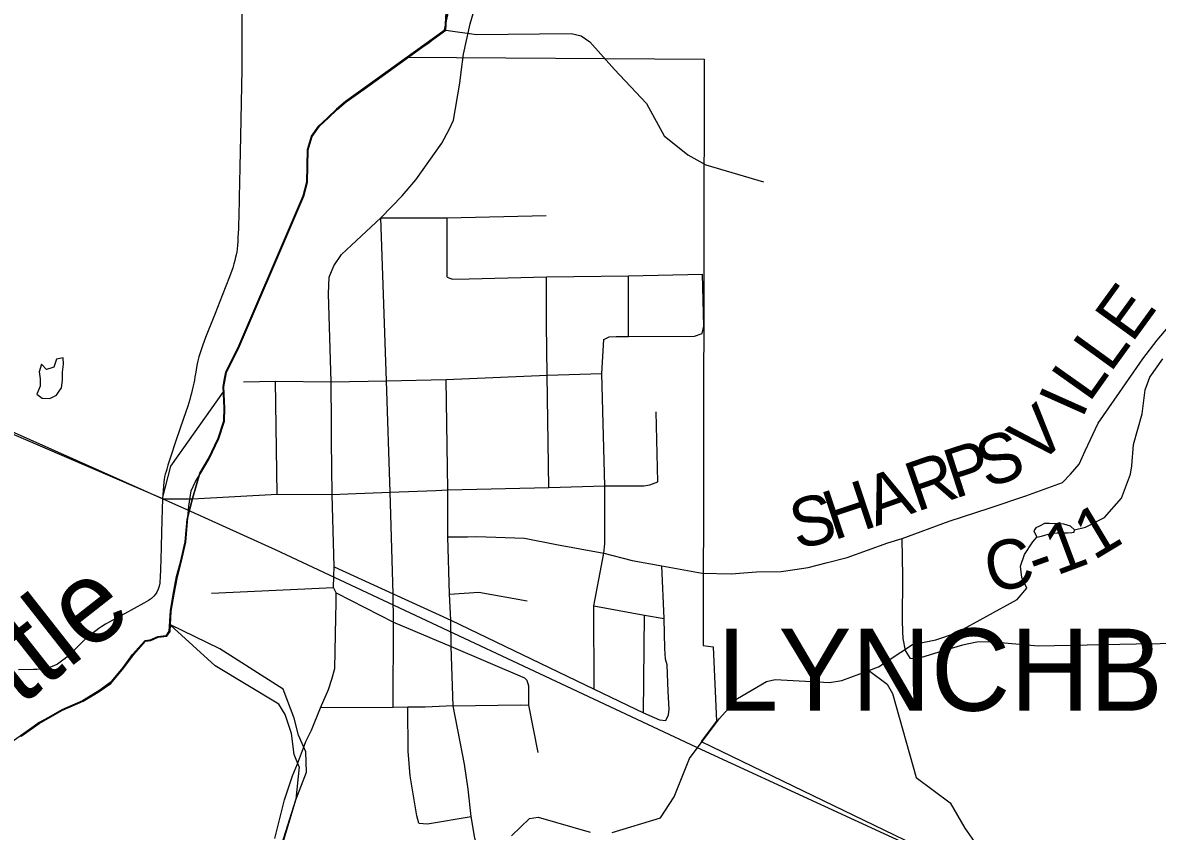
# Model space of a CAD drawing. Extents: x 0 to 1052, y -194 to 246.
# Drawn here: x 2.825 to 4.134, y 14.787 to 15.72 of the extents above; entities that cross this region are included whole.
import ezdxf

# ---------------------------------------------------------------- set-up
doc = ezdxf.new("R2010")
doc.units = 0
for name, color, linetype in [('GM_X_City_Street', 7, 'Continuous'), ('GM_X_Corporation', 7, 'Continuous'), ('GM_X_Corporation_Text', 7, 'Continuous'), ('GM_X_County_Road', 7, 'Continuous'), ('GM_X_County_Road_Text', 7, 'Continuous'), ('GM_X_Major_River', 7, 'Continuous'), ('GM_X_Major_River_Text', 7, 'Continuous'), ('GM_X_Minor_Lake', 7, 'Continuous'), ('GM_X_Minor_River', 7, 'Continuous'), ('GM_X_Rail_Line', 7, 'Continuous'), ('GM_X_State_Route', 7, 'Continuous'), ('GM_X_Township_Road', 7, 'Continuous')]:
    doc.layers.add(name, color=color, linetype=linetype)

msp = doc.modelspace()

# ---------------------------------------------------------------- linework, layer by layer
at = {"layer": 'GM_X_City_Street'}
for p, q in [((3.3148, 15.4262), (3.3148, 15.4949)), ((3.5238, 15.358), (3.5241, 15.4277)), ((3.1186, 15.1761), (3.1169, 15.3065)), ((3.5577, 15.1904), (3.556, 15.271)), ((3.3154, 15.1268), (3.3155, 15.172)), ((3.0431, 15.0619), (3.1835, 15.0686)), ((3.5414, 14.9237), (3.5423, 15.0365)), ((3.4087, 14.9328), (3.4193, 14.8783))]:
    msp.add_line(p, q, dxfattribs=at)
for points in [[(3.2384, 15.4949), (3.3148, 15.4949), (3.4288, 15.4973)], [(3.2525, 14.9299), (3.2529, 15.0284), (3.2524, 15.0612), (3.2491, 15.1784), (3.2447, 15.3069), (3.2384, 15.4949)], [(3.3148, 15.4262), (3.3209, 15.4238), (3.3402, 15.4242), (3.4293, 15.4266), (3.5241, 15.4277), (3.6094, 15.4299)], [(3.609, 15.3612), (3.6108, 15.3696), (3.6094, 15.4299)], [(3.4322, 15.1839), (3.4302, 15.3134), (3.4293, 15.372), (3.4293, 15.4266)], [(3.4844, 14.9511), (3.4841, 15.0474), (3.4956, 15.1079), (3.4966, 15.1187), (3.4967, 15.1858), (3.4933, 15.3152), (3.4953, 15.3544)], [(3.4953, 15.3544), (3.5015, 15.3573), (3.5098, 15.358), (3.5238, 15.358), (3.6002, 15.3582), (3.609, 15.3612)], [(3.0797, 15.3056), (3.1169, 15.3065), (3.1808, 15.3057), (3.2447, 15.3069), (3.3136, 15.3082), (3.4302, 15.3134), (3.4933, 15.3152)], [(3.3155, 15.172), (3.3155, 15.1811), (3.3136, 15.3082)], [(3.2001, 15.1764), (3.2491, 15.1784), (3.3017, 15.1804), (3.3155, 15.1811), (3.4322, 15.1839), (3.4967, 15.1858), (3.5417, 15.1857), (3.5486, 15.187), (3.5577, 15.1904)], [(3.0212, 15.1706), (3.1186, 15.1761), (3.1822, 15.1756), (3.2001, 15.1764)], [(3.3154, 15.1268), (3.3381, 15.1269), (3.3486, 15.1272), (3.4039, 15.1254), (3.4408, 15.1179), (3.4956, 15.1079), (3.5282, 15.0994), (3.5624, 15.0933)], [(3.3215, 14.9319), (3.3194, 15.0003), (3.3188, 15.0309), (3.3175, 15.0606), (3.3154, 15.1268)], [(3.1843, 15.0923), (3.2524, 15.0612), (3.3188, 15.0309), (3.4844, 14.9511), (3.5414, 14.9237), (3.5596, 14.916), (3.567, 14.9151)], [(3.566, 14.9979), (3.5651, 15.0326), (3.5624, 15.0933)], [(3.1869, 15.0623), (3.2529, 15.0284), (3.3194, 15.0003), (3.4038, 14.9643), (3.4066, 14.9617), (3.4087, 14.9552), (3.4087, 14.9328)], [(3.3175, 15.0606), (3.3512, 15.063), (3.4072, 15.0532)], [(3.4841, 15.0474), (3.5423, 15.0365), (3.5651, 15.0326)], [(3.567, 14.9151), (3.5699, 14.9215), (3.5708, 14.9282), (3.5696, 14.9484), (3.5686, 14.9791), (3.5664, 14.9859), (3.566, 14.9979)], [(3.3215, 14.9319), (3.3991, 14.9333), (3.4087, 14.9328)], [(3.2819, 14.7965), (3.2796, 14.805), (3.2721, 14.8511), (3.2698, 14.8796), (3.2693, 14.9304)], [(3.2819, 14.7965), (3.2922, 14.7957), (3.3425, 14.8045)]]:
    msp.add_lwpolyline(points, dxfattribs=at)
at = {"layer": 'GM_X_Corporation'}
for points in [[(3.3184, 15.8132), (3.3123, 15.7116), (3.1976, 15.629), (3.1871, 15.6201), (3.1767, 15.61), (3.1666, 15.6007), (3.1584, 15.5887), (3.1536, 15.5736), (3.1532, 15.5546), (3.1528, 15.5364), (3.1487, 15.5201), (3.136, 15.4904), (3.0743, 15.3472), (3.0593, 15.3167), (3.0576, 15.3073), (3.0563, 15.3), (3.0574, 15.2757), (3.0571, 15.2605), (3.0506, 15.2405), (3.0395, 15.2172), (3.0293, 15.2003), (3.0209, 15.1712), (3.0148, 15.1473), (3.0126, 15.1212), (3.0072, 15.0977), (3.0027, 15.0811), (2.9988, 15.0604), (2.9955, 15.0414), (2.9943, 15.0182), (2.9908, 15.0126), (2.9805, 15.0116), (2.972, 15.0076), (2.966, 15.007), (2.952, 14.9913), (2.9411, 14.9763), (2.9259, 14.958), (2.9112, 14.948), (2.894, 14.9377), (2.8702, 14.9272), (2.8433, 14.9121), (2.8225, 14.8973)], [(2.8225, 14.8973), (2.8433, 14.9121), (2.8702, 14.9272), (2.894, 14.9377), (2.9112, 14.948), (2.9259, 14.958), (2.9411, 14.9763), (2.952, 14.9913), (2.966, 15.007), (2.972, 15.0076), (2.9805, 15.0116), (2.9908, 15.0126), (2.9943, 15.0182), (2.9955, 15.0414), (2.9988, 15.0604), (3.0027, 15.0811), (3.0072, 15.0977), (3.0126, 15.1212), (3.0148, 15.1473), (3.0209, 15.1712), (3.0293, 15.2003), (3.0395, 15.2172), (3.0506, 15.2405), (3.0571, 15.2605), (3.0574, 15.2757), (3.0563, 15.3), (3.0576, 15.3073), (3.0593, 15.3167), (3.0743, 15.3472), (3.136, 15.4904), (3.1487, 15.5201), (3.1528, 15.5364), (3.1532, 15.5546), (3.1536, 15.5736), (3.1584, 15.5887), (3.1666, 15.6007), (3.1767, 15.61), (3.1871, 15.6201), (3.1976, 15.629), (3.3123, 15.7116), (3.3184, 15.8132)], [(2.8225, 14.8973), (2.8433, 14.9121), (2.8702, 14.9272), (2.894, 14.9377), (2.9112, 14.948), (2.9259, 14.958), (2.9411, 14.9763), (2.952, 14.9913), (2.966, 15.007), (2.972, 15.0076), (2.9805, 15.0116), (2.9908, 15.0126), (2.9943, 15.0182), (2.9955, 15.0414), (2.9988, 15.0604), (3.0027, 15.0811), (3.0072, 15.0977), (3.0126, 15.1212), (3.0148, 15.1473), (3.0209, 15.1712), (3.0293, 15.2003), (3.0395, 15.2172), (3.0506, 15.2405), (3.0571, 15.2605), (3.0574, 15.2757), (3.0563, 15.3), (3.0576, 15.3073), (3.0593, 15.3167), (3.0743, 15.3472), (3.136, 15.4904), (3.1487, 15.5201), (3.1528, 15.5364), (3.1532, 15.5546), (3.1536, 15.5736), (3.1584, 15.5887), (3.1666, 15.6007), (3.1767, 15.61), (3.1871, 15.6201), (3.1976, 15.629), (3.3123, 15.7116), (3.3184, 15.8132)], [(3.3184, 15.8132), (3.3123, 15.7116), (3.1976, 15.629), (3.1871, 15.6201), (3.1767, 15.61), (3.1666, 15.6007), (3.1584, 15.5887), (3.1536, 15.5736), (3.1532, 15.5546), (3.1528, 15.5364), (3.1487, 15.5201), (3.136, 15.4904), (3.0743, 15.3472), (3.0593, 15.3167), (3.0576, 15.3073), (3.0563, 15.3), (3.0574, 15.2757), (3.0571, 15.2605), (3.0506, 15.2405), (3.0395, 15.2172), (3.0293, 15.2003), (3.0209, 15.1712), (3.0148, 15.1473), (3.0126, 15.1212), (3.0072, 15.0977), (3.0027, 15.0811), (2.9988, 15.0604), (2.9955, 15.0414), (2.9943, 15.0182), (2.9908, 15.0126), (2.9805, 15.0116), (2.972, 15.0076), (2.966, 15.007), (2.952, 14.9913), (2.9411, 14.9763), (2.9259, 14.958), (2.9112, 14.948), (2.894, 14.9377), (2.8702, 14.9272), (2.8433, 14.9121), (2.8225, 14.8973)], [(2.712, 15.289), (2.9863, 15.171), (2.9962, 15.2083), (3.0566, 15.294), (3.0563, 15.3), (3.0593, 15.3167), (3.0743, 15.3472), (3.136, 15.4904), (3.1487, 15.5201), (3.1528, 15.5364), (3.1532, 15.5546), (3.1536, 15.5736), (3.1584, 15.5887), (3.1666, 15.6007), (3.1767, 15.61), (3.1871, 15.6201), (3.1976, 15.629), (3.2683, 15.6799), (3.6112, 15.6776), (3.6101, 15.0015), (3.6214, 14.9999), (3.6253, 14.9144), (3.6079, 14.891), (3.936, 14.7322)], [(3.1195, 14.758), (3.1403, 14.8235), (3.1526, 14.8554), (3.1519, 14.879), (3.1434, 14.8982), (3.1382, 14.9177), (3.1256, 14.951), (3.0526, 14.9976), (2.9947, 15.0257), (2.9943, 15.0182), (2.9908, 15.0126), (2.9848, 15.012), (2.9805, 15.0116), (2.9721, 15.0076), (2.966, 15.007), (2.959, 14.9993), (2.9482, 14.9861), (2.9394, 14.9743), (2.9273, 14.9597), (2.9114, 14.9481), (2.8932, 14.937), (2.8707, 14.9273), (2.8607, 14.9215), (2.8442, 14.9126), (2.8341, 14.9056), (2.8001, 14.8813)]]:
    msp.add_lwpolyline(points, dxfattribs=at)
at = {"layer": 'GM_X_County_Road'}
for p, q in [((2.9868, 15.1754), (2.9865, 15.1705)), ((3.5624, 15.0933), (3.6087, 15.0851))]:
    msp.add_line(p, q, dxfattribs=at)
for points in [[(3.0774, 15.7661), (3.0779, 15.7101), (3.0778, 15.666), (3.0763, 15.5884), (3.0756, 15.5536), (3.0752, 15.535), (3.0749, 15.5188), (3.0743, 15.4943), (3.0741, 15.4888), (3.074, 15.4847), (3.0739, 15.4816), (3.0737, 15.4775), (3.0735, 15.4716), (3.0734, 15.4673), (3.073, 15.4633), (3.0726, 15.4587), (3.0721, 15.4556), (3.0715, 15.4521), (3.0708, 15.4492), (3.0699, 15.4455), (3.0687, 15.4415), (3.0674, 15.4372), (3.0637, 15.4267), (3.0554, 15.4053), (3.047, 15.3845), (3.0361, 15.3568), (3.0329, 15.3481), (3.0309, 15.3426), (3.0297, 15.3392), (3.0282, 15.3344), (3.0272, 15.3299), (3.0265, 15.3265), (3.0258, 15.3223), (3.0248, 15.3167), (3.0238, 15.3113), (3.0232, 15.3075), (3.0224, 15.3039), (3.0216, 15.2996), (3.0207, 15.2961), (3.0198, 15.2924), (3.0189, 15.2888), (3.0179, 15.2854), (3.0155, 15.2775), (3.0108, 15.2634), (3.0019, 15.2376), (2.9952, 15.2175), (2.9942, 15.2141), (2.9927, 15.2093), (2.9914, 15.2049), (2.9905, 15.202), (2.9896, 15.1993), (2.9889, 15.1962), (2.9882, 15.1929), (2.988, 15.1901), (2.9868, 15.1754)], [(3.6087, 15.0851), (3.6424, 15.0841), (3.6716, 15.0863), (3.7, 15.087), (3.7156, 15.0891), (3.7312, 15.0915), (3.7519, 15.0967), (3.776, 15.103), (3.8229, 15.12), (3.8396, 15.1248), (3.8936, 15.1448), (3.9398, 15.1599), (3.9823, 15.174), (4.0244, 15.1896), (4.0339, 15.1993), (4.0439, 15.2108), (4.0505, 15.2261), (4.0657, 15.2581), (4.0901, 15.2933), (4.1172, 15.3323), (4.1336, 15.3538), (4.1462, 15.3686)], [(2.9865, 15.1705), (2.9855, 15.146), (2.9849, 15.1162), (2.9845, 15.1), (2.9842, 15.0907), (2.9837, 15.0789), (2.9835, 15.0766), (2.9832, 15.0734), (2.9825, 15.0699), (2.9814, 15.0664), (2.9798, 15.0632), (2.9783, 15.0606), (2.9764, 15.0583), (2.9737, 15.0559), (2.9702, 15.0534), (2.965, 15.0502), (2.9426, 15.0381), (2.9327, 15.0328), (2.9284, 15.0305), (2.9248, 15.0285), (2.9208, 15.0261), (2.9164, 15.0234), (2.9129, 15.0211), (2.9095, 15.0186), (2.9063, 15.0163), (2.9029, 15.0135), (2.9, 15.0111), (2.894, 15.0056), (2.8794, 14.9913), (2.8769, 14.989), (2.8743, 14.9867), (2.8715, 14.9845), (2.8685, 14.9822), (2.8653, 14.9801), (2.8611, 14.978), (2.8579, 14.9768), (2.8548, 14.9758), (2.8505, 14.9749), (2.8458, 14.9742), (2.8416, 14.974), (2.8378, 14.9737), (2.8204, 14.9736)], [(2.9865, 15.1705), (3.0035, 15.1705), (3.0212, 15.1706)]]:
    msp.add_lwpolyline(points, dxfattribs=at)
at = {"layer": 'GM_X_Major_River'}
for points in [[(3.3131, 15.7113), (3.3192, 15.8129), (3.3722, 15.9077), (3.4672, 15.9911), (3.5089, 16.1815), (3.563, 16.2763), (3.5868, 16.3714), (3.6039, 16.5262)], [(3.2172, 15.6426), (3.2252, 15.6485), (3.2655, 15.6778), (3.2939, 15.6969), (3.3118, 15.7115), (3.3234, 15.7637)], [(3.2189, 15.643), (3.3131, 15.7113)], [(2.8233, 14.897), (2.8441, 14.9117), (2.871, 14.9268), (2.8948, 14.9374), (2.9121, 14.9477), (2.9267, 14.9576), (2.9419, 14.9759), (2.9528, 14.9909), (2.9668, 15.0066), (2.9729, 15.0073), (2.9813, 15.0113), (2.9916, 15.0122), (2.9951, 15.0178), (2.9963, 15.041), (2.9997, 15.0607), (3.0036, 15.0808), (3.0081, 15.0974), (3.0134, 15.1208), (3.0154, 15.1444), (3.0169, 15.1622), (3.0195, 15.18), (3.0243, 15.1905), (3.0302, 15.1999), (3.0404, 15.2168), (3.0515, 15.2402), (3.0579, 15.2602), (3.0582, 15.2754), (3.0572, 15.2997), (3.0602, 15.3164), (3.0752, 15.3468), (3.1368, 15.49), (3.1496, 15.5198), (3.1537, 15.536), (3.154, 15.5543), (3.1544, 15.5733), (3.1592, 15.5884), (3.1675, 15.6004), (3.1775, 15.6097), (3.188, 15.6197), (3.1984, 15.6286), (3.2189, 15.643)], [(2.8233, 14.897), (2.8441, 14.9117), (2.871, 14.9268), (2.8948, 14.9374), (2.9121, 14.9477), (2.9267, 14.9576), (2.9419, 14.9759), (2.9528, 14.9909), (2.9668, 15.0066), (2.9729, 15.0073), (2.9813, 15.0113), (2.9916, 15.0122), (2.9951, 15.0178), (2.9963, 15.041), (2.9997, 15.0607), (3.0036, 15.0808), (3.0081, 15.0974), (3.0134, 15.1208), (3.0154, 15.1444), (3.0169, 15.1622), (3.0195, 15.18), (3.0243, 15.1905), (3.0302, 15.1999), (3.0404, 15.2168), (3.0515, 15.2402), (3.0579, 15.2602), (3.0582, 15.2754), (3.0572, 15.2997), (3.0602, 15.3164), (3.0752, 15.3468), (3.1368, 15.49), (3.1496, 15.5198), (3.1537, 15.536), (3.154, 15.5543), (3.1544, 15.5733), (3.1592, 15.5884), (3.1675, 15.6004), (3.1775, 15.6097), (3.188, 15.6197), (3.1984, 15.6286), (3.2172, 15.6426)]]:
    msp.add_lwpolyline(points, dxfattribs=at)
at = {"layer": 'GM_X_Minor_Lake'}
for points in [[(2.8587, 15.3218), (2.8525, 15.3199), (2.8469, 15.326), (2.8441, 15.3173), (2.8455, 15.309), (2.8455, 15.3006), (2.8416, 15.2915), (2.8476, 15.2869), (2.8563, 15.2865), (2.8643, 15.2902), (2.8664, 15.2938)], [(2.8664, 15.2938), (2.8701, 15.2988), (2.871, 15.3076), (2.871, 15.3167), (2.8723, 15.3258), (2.872, 15.3334), (2.864, 15.3316), (2.8609, 15.3225), (2.8587, 15.3218)], [(3.9949, 15.1264), (4.0003, 15.1278), (4.0106, 15.1307), (4.0182, 15.1313), (4.0258, 15.1315), (4.0303, 15.1314), (4.0352, 15.1317), (4.0379, 15.1324), (4.0383, 15.1351), (4.0339, 15.1393), (4.0259, 15.1414), (4.0195, 15.1419), (4.0096, 15.1421), (4.0036, 15.1422), (3.9978, 15.1393), (3.9936, 15.1374), (3.9916, 15.1337)], [(3.9916, 15.1337), (3.9949, 15.1264)]]:
    msp.add_lwpolyline(points, dxfattribs=at)
at = {"layer": 'GM_X_Minor_River'}
for points in [[(3.3131, 15.7113), (3.3485, 15.7062), (3.4577, 15.7071), (3.4695, 15.7047), (3.4792, 15.6977), (3.5077, 15.6659), (3.5448, 15.6265)], [(3.5448, 15.6265), (3.565, 15.5893), (3.5922, 15.5675), (3.6132, 15.5557), (3.6796, 15.5362)], [(4.0383, 15.1351), (4.0509, 15.1379), (4.0728, 15.1492), (4.0926, 15.1716), (4.103, 15.1991), (4.1043, 15.2089), (4.1063, 15.2332), (4.1165, 15.2687), (4.1197, 15.2963), (4.1253, 15.311), (4.1401, 15.332)], [(3.5049, 14.7859), (3.561, 14.8027), (3.5766, 14.8271), (3.5942, 14.8711), (3.6285, 14.9171), (3.6498, 14.9403), (3.6832, 14.9601), (3.6931, 14.9622), (3.7556, 14.9587), (3.7701, 14.9611), (3.8011, 14.9727), (3.8121, 14.977), (3.8514, 15.0028), (3.8784, 15.008), (3.9021, 15.0163), (3.9723, 15.0547), (3.9835, 15.0678), (3.9777, 15.0801), (3.9761, 15.093), (3.9805, 15.1066), (3.9903, 15.1212), (3.9949, 15.1264)], [(3.144, 14.8616), (3.1382, 14.8757), (3.1352, 14.9001), (3.1281, 14.9218), (3.1207, 14.9337), (3.0472, 14.978), (2.9955, 15.0249)], [(3.8011, 14.9727), (3.8224, 14.9571), (3.8286, 14.9463), (3.8556, 14.8494), (3.8948, 14.8202), (3.9117, 14.7907), (3.9413, 14.7487), (3.9551, 14.7405), (3.9917, 14.7273), (4.0025, 14.7172), (4.0188, 14.6767), (4.0359, 14.6403), (4.0606, 14.6212), (4.0824, 14.6121), (4.1084, 14.6218), (4.1304, 14.6411), (4.1461, 14.648), (4.18, 14.6542), (4.1921, 14.6551), (4.2135, 14.66), (4.2258, 14.6685), (4.2359, 14.6816), (4.2478, 14.6908), (4.2704, 14.6995)], [(3.144, 14.8616), (3.1402, 14.8244), (3.1203, 14.7577)], [(3.3891, 14.7821), (3.4096, 14.8022), (3.4198, 14.8035), (3.4798, 14.7864)]]:
    msp.add_lwpolyline(points, dxfattribs=at)
at = {"layer": 'GM_X_Rail_Line'}
for points in [[(1.9822, 15.6192), (2.2465, 15.5027), (2.5441, 15.3677), (3.0187, 15.1565)], [(3.0187, 15.1565), (3.1162, 15.1123), (3.6083, 14.8817), (4.1755, 14.6202), (5.0257, 14.2265), (5.0707, 14.2055)]]:
    msp.add_lwpolyline(points, dxfattribs=at)
at = {"layer": 'GM_X_State_Route'}
for points in [[(3.3309, 15.6626), (3.3336, 15.6833), (3.3412, 15.7185), (3.3559, 15.7688), (3.3684, 15.8107), (3.3766, 15.8444), (3.3998, 15.8752), (3.4222, 15.9019), (3.4438, 15.9251), (3.4554, 15.9436), (3.5244, 16.0224), (3.5876, 16.0907), (3.6204, 16.1297), (3.6481, 16.1593), (3.6582, 16.1782), (3.6834, 16.5002), (3.6924, 16.5782), (3.6966, 16.5945)], [(3.2044, 15.4632), (3.2384, 15.4949), (3.2627, 15.52), (3.2785, 15.5387), (3.3087, 15.5808), (3.3172, 15.5964), (3.322, 15.6075), (3.3292, 15.6499), (3.3309, 15.6626)], [(3.1812, 15.2568), (3.1808, 15.3057), (3.1778, 15.4069), (3.1788, 15.4262), (3.1839, 15.4394), (3.193, 15.4526), (3.2044, 15.4632)], [(3.184, 15.0814), (3.1843, 15.0923), (3.1822, 15.1756), (3.1814, 15.2373), (3.1812, 15.2568)], [(3.1863, 15.034), (3.1867, 15.0507), (3.1869, 15.0623), (3.1835, 15.0686), (3.184, 15.0814)], [(3.149, 14.8834), (3.1517, 14.8907), (3.1581, 14.9039), (3.1686, 14.9295), (3.1779, 14.9507), (3.1817, 14.9629), (3.1851, 14.975), (3.1863, 15.034)], [(3.3215, 14.9319), (3.2893, 14.9306), (3.2693, 14.9304), (3.2525, 14.9299), (3.1686, 14.9295)], [(3.3478, 14.7754), (3.3467, 14.7793), (3.3425, 14.8045), (3.339, 14.8358), (3.3346, 14.8647), (3.3215, 14.9319)], [(3.1161, 14.7789), (3.1273, 14.8235), (3.1364, 14.8514), (3.1422, 14.865), (3.149, 14.8834)]]:
    msp.add_lwpolyline(points, dxfattribs=at)
at = {"layer": 'GM_X_Township_Road'}
for points in [[(3.8404, 15.0176), (3.8399, 15.0304), (3.8403, 15.0811), (3.8396, 15.1248)], [(3.855, 14.9861), (3.8492, 14.9864), (3.8436, 14.9957), (3.8407, 15.0097), (3.8404, 15.0176)], [(4.1925, 15.0044), (4.1096, 15.0031), (3.9964, 15.0008), (3.9402, 15.0057), (3.9257, 15.0053), (3.9091, 15.002), (3.8858, 14.9949), (3.8569, 14.9861), (3.855, 14.9861)]]:
    msp.add_lwpolyline(points, dxfattribs=at)

# ---------------------------------------------------------------- texts
at = {"layer": 'GM_X_Corporation_Text'}
msp.add_text('LYNCHBURG', height=0.0947, rotation=0, dxfattribs=at).set_placement((3.6264, 14.9263))
at = {"layer": 'GM_X_County_Road_Text'}
for s, rotation, p in [('E', 54.007, (4.1046, 15.3495)), ('L', 54.0481, (4.0797, 15.3151)), ('L', 54.6843, (4.0552, 15.2806)), ('I', 65.9273, (4.0471, 15.2619)), ('V', 42.2495, (3.9952, 15.2076)), ('S', 18.3857, (3.9367, 15.1826)), ('P', 18.1983, (3.9, 15.1705)), ('R', 19.0231, (3.8561, 15.1554)), ('A', 19.5248, (3.8091, 15.1387)), ('H', 18.4892, (3.7606, 15.1225)), ('S', 13.1581, (3.7178, 15.1122)), ('1', 30.9659, (4.0604, 15.0991)), ('1', 20.5179, (4.0175, 15.0819)), ('C', 12.5064, (3.9416, 15.0615)), ('-', 19.6001, (3.9946, 15.0738))]:
    msp.add_text(s, height=0.0568, rotation=rotation, dxfattribs=at).set_placement(p)
at = {"layer": 'GM_X_Major_River_Text'}
msp.add_text('Little', height=0.0947, rotation=38.1806, dxfattribs=at).set_placement((2.7444, 14.8695))

doc.saveas('drawing.dxf')
